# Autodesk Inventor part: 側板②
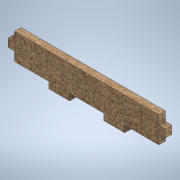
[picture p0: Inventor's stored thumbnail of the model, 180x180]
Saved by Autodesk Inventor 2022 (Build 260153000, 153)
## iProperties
Created: 2024-11
Part Number: 側板②
Material: MDF 中密度繊維ボード
Document SubType Name: Modeling
Designer: shimizu
Density: 0.8 g/cm^3
Appearance: ダンボール - 段ボール紙
Author: shimizu
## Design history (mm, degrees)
sketch "スケッチ1"
  geometry: L1 (-25.358, 1.343)-(29.642, 1.343); L2 (-4.358, -8.657)-(-4.358, -11.157); L3 (-4.358, -11.157)-(-12.358, -11.157); L4 (-12.358, -11.157)-(-12.358, -8.657); L5 (16.642, -8.657)-(16.642, -11.157); L6 (16.642, -11.157)-(8.642, -11.157); L7 (8.642, -11.157)-(8.642, -8.657); L8 (-25.358, -2.157)-(-27.858, -2.157); L9 (-27.858, -2.157)-(-27.858, -5.157); L10 (-27.858, -5.157)-(-25.358, -5.157); L11 (29.642, -2.157)-(32.142, -2.157); L12 (32.142, -2.157)-(32.142, -5.157); L13 (32.142, -5.157)-(29.642, -5.157); L14 (-25.358, -8.657)-(-25.358, -5.157); L15 (-25.358, -2.157)-(-25.358, 1.343); L16 (29.642, 1.343)-(29.642, -2.157); L17 (29.642, -5.157)-(29.642, -8.657); L18 (29.642, -8.657)-(16.642, -8.657); L19 (8.642, -8.657)-(-4.358, -8.657); L20 (-12.358, -8.657)-(-25.358, -8.657); 1 further point
  constraints: 40 end point, 11 parallel, 4 perpendicular, 3 horizontal
  dimensions: "d16" = 13 distance of L17.end L5.start; "d17" = 13 distance of L4.end L14.start; "d18" = 8 distance of L5.end L6.end; "d19" = 8 distance of L2.end L3.end; "d20" = 13 distance of L7.end L2.start; "d21" = 55 distance between parallel lines of L16 L15; "d22" = 60 distance between parallel lines of L12 L9
extrude "押し出し1" new body sketch "スケッチ1" distance "d14" = 2.5; taper "d15" = 0 deg
node "ソリッド1"
